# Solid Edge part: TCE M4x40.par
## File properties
Title: 43200131ZN
Subject: Vite TCEI M4x40 zincata
Author: g_deluca
Template: RBuno.par
Last saved by: g_deluca
Revision: 12
Application: Solid Edge
Company: EFFEBI S.p.A.
Codice: Codice
Indice rev.: Rev.
Data rev.: Data rev.
Firma rev.: Firma rev.
Descrizione rev.: Descrizione rev.
Densità: 7860.000 kg/m^3
Precisione: 0.99
Tipo di contenuto documento: 0
Document Number: UNI 5931
Material: Classe 8.8
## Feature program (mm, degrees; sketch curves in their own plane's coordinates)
sketch for "unnamed Protrusion 1" plane through (0, 0, 0) normal (0, 0, 1) x-axis (1, 0, 0)
extrude "unnamed Protrusion 1" add finite 4 along +normal
sketch for "ExtrudedProtrusion_3" plane through (0, 0, 0) normal (0, 0, 1) x-axis (1, 0, 0)
  circle centre (0, 0) radius 2
extrude "ExtrudedProtrusion_3" add finite 40 along -normal
sketch for "unnamed RevolvedCutout 1" plane through (0, 0, 0) normal (0, -1, 0) x-axis (1, 0, 0)
revolve "unnamed RevolvedCutout 1" cut full turn 360 deg about sketch line (0, -40) -> (0, -26)
sketch for "ExtrudedCutout_1" plane through (0, 0, 4) normal (0, 0, 1) x-axis (0, 1, 0)
  line (-1.5, 0.866) -> (-1.5, -0.866)
  line (-1.5, -0.866) -> (0, -1.7321)
  line (0, -1.7321) -> (1.5, -0.866)
  line (1.5, -0.866) -> (1.5, 0.866)
  line (1.5, 0.866) -> (0, 1.7321)
  line (0, 1.7321) -> (-1.5, 0.866)
extrude "ExtrudedCutout_1" cut finite 3 along -normal
chamfer "Chamfer_1" setback 0.25
thread "unnamed Thread 1"
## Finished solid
Body 1: solid body, 18 faces, 28 edges, 12 vertices.
  Faces by surface: plane 11, cylinder 4, cone 3
  Edges by curve: line 18, circle 10
Bounding box of the edges (mm): 7.000 x 7.000 x 44.000, from (-3.5, -3.5, -40) to (3.5, 3.5, 4).
Cylindrical faces by radius (mm): R1.995 x1, R2 x2, R3.5 x1
Conical faces (half-angle, radius in mm at the cone's reference point): 45 deg R1.75 x1, 45 deg R1.995 x1, 45 deg R3.5 x1
Planar faces by outward normal: +y 1, +z 3, -y 1, -z 2, oblique 4
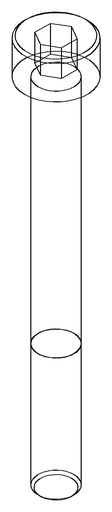
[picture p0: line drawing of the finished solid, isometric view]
